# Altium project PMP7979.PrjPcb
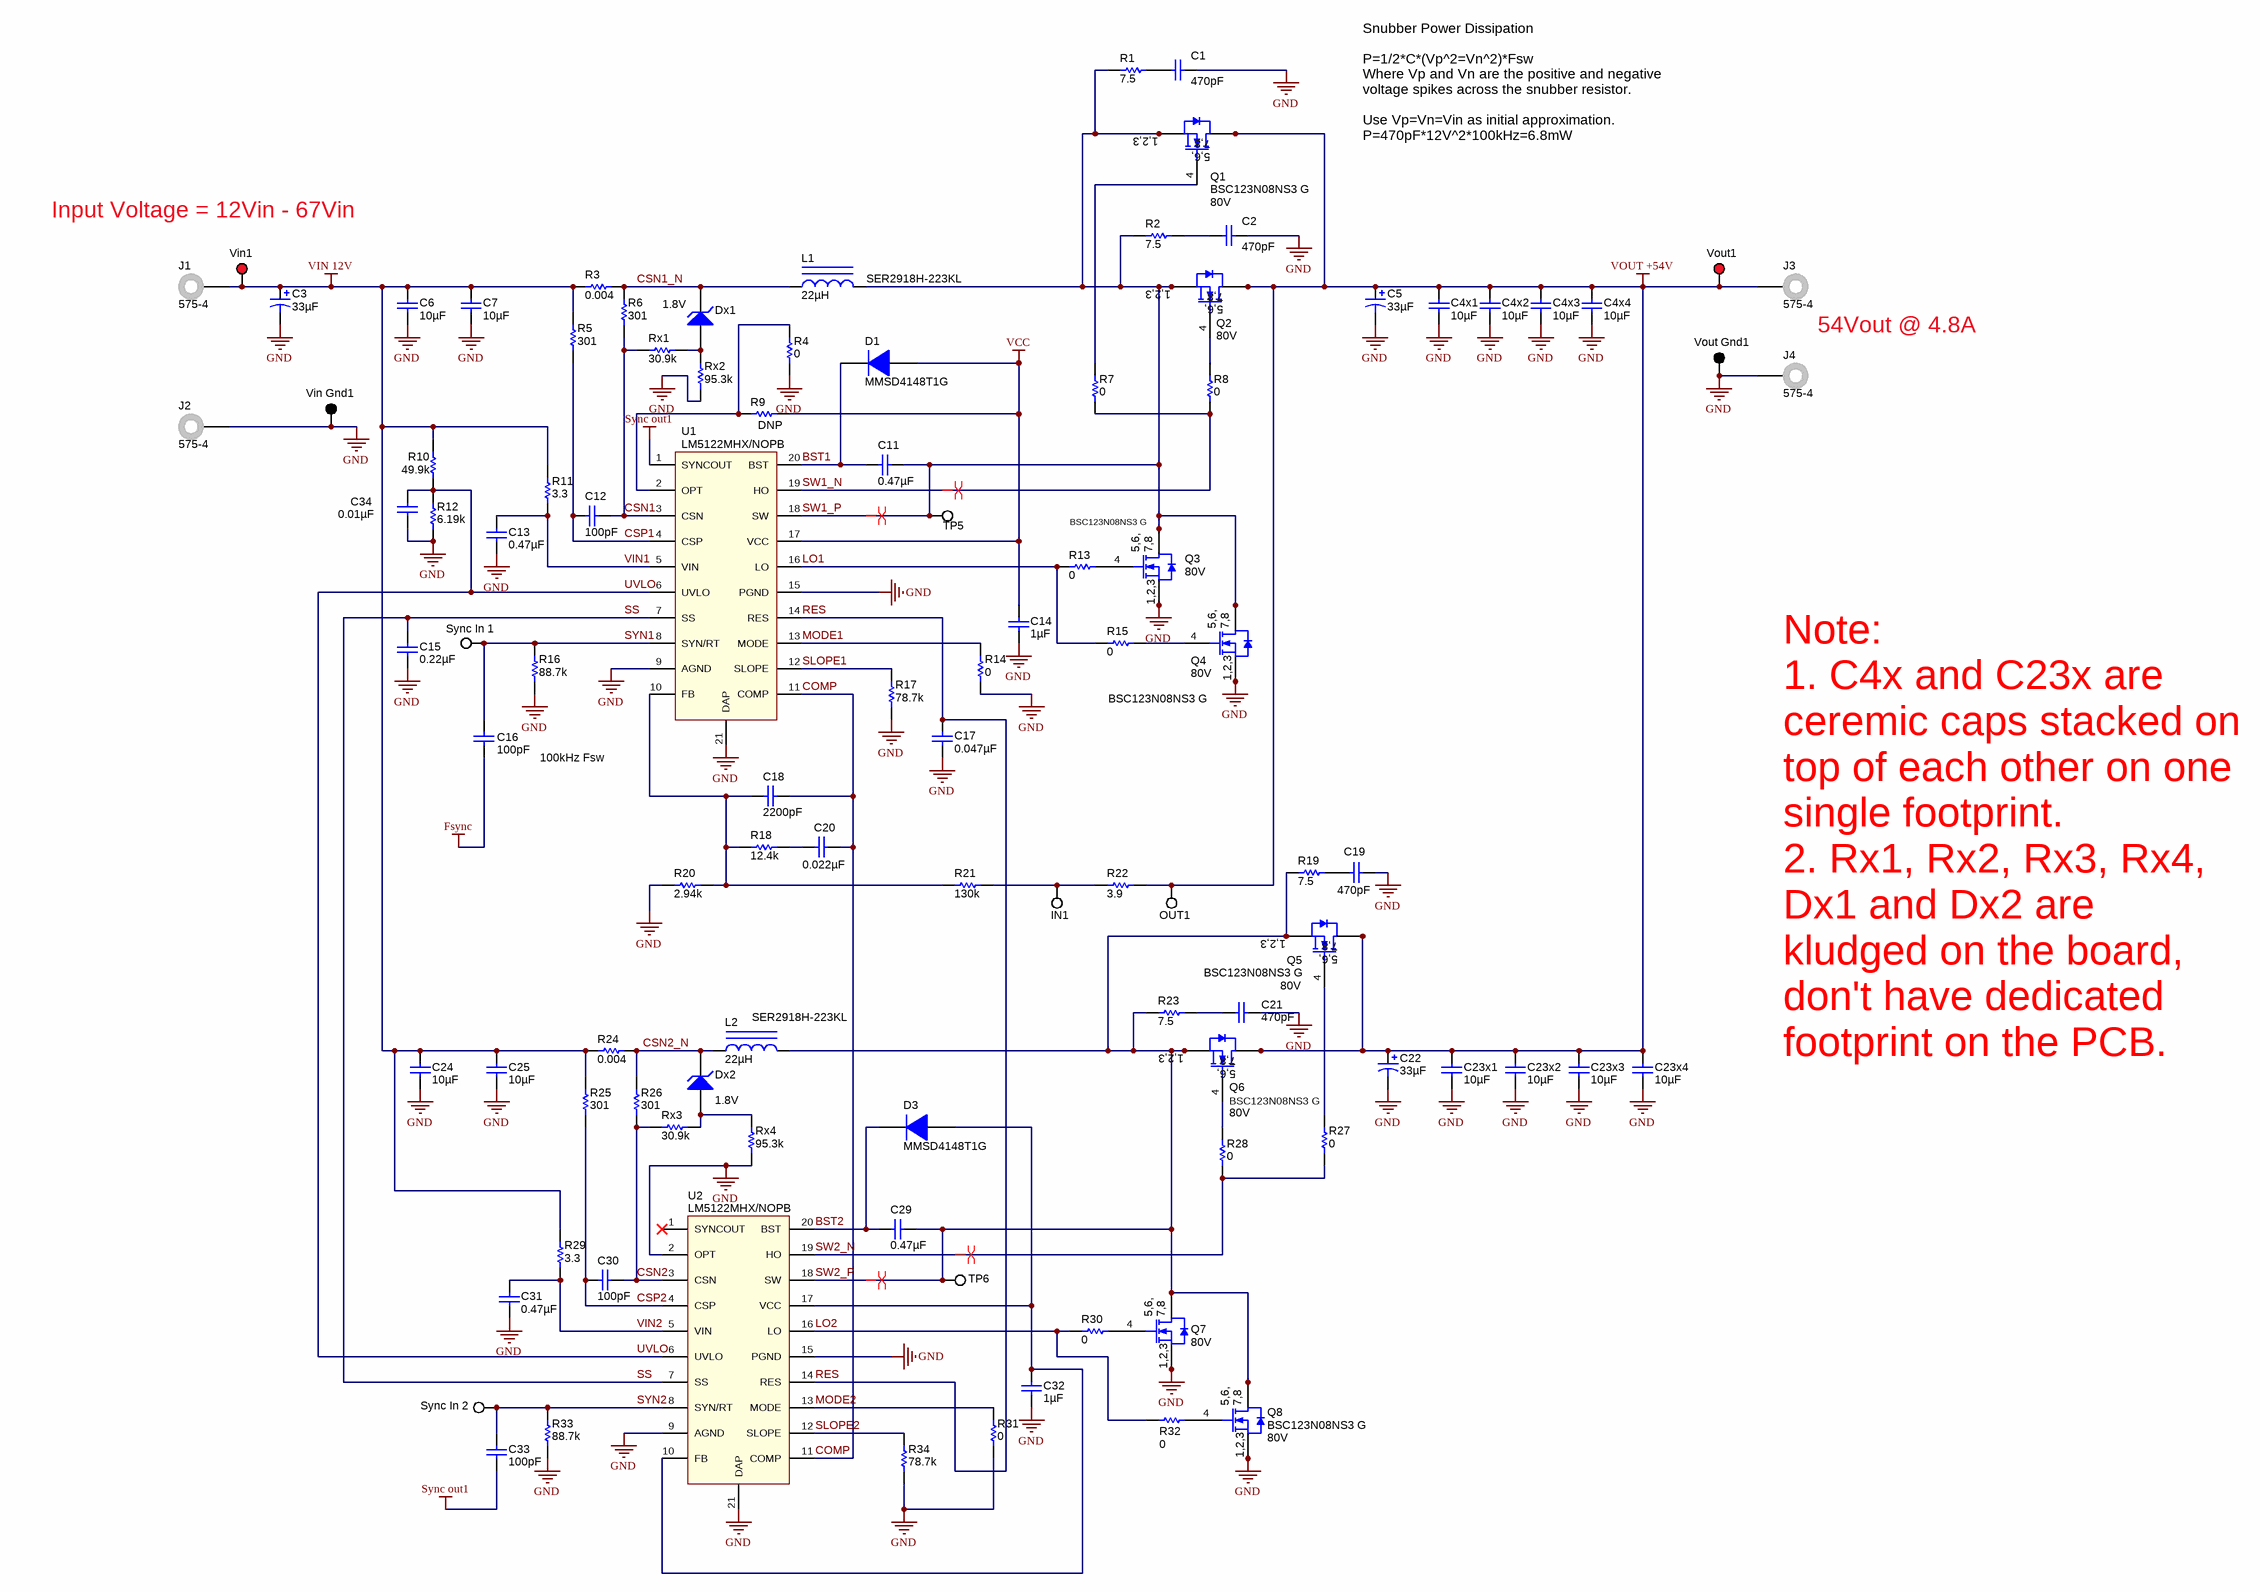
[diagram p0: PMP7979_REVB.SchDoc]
CopyrightYear: 2015; EVM_Orderable: N/A; PCB_Layout: David Baba; PCB_Rev: B; PRJ_Customer: Public Release; PRJ_Engineer: Xinyu Dai; PRJ_Number: PMP7979; PRJ_Title: LM5122 Dual Phase Boost; SCH_Rev: B; TechSupport: http://www.ti.com/support; TID: PMP7979
2 sheets, 111 parts. Net scope: global (net labels, ports and power ports of the same name join across sheets).
Board file: PMP7850 REVB.PcbDoc
Sheets:
  PMP7979_REVB.SchDoc
  PMP7979_Hardware_REVB.SchDoc

## Sheet PMP7979_REVB.SchDoc
size 558 x 431 mm; Date: Not shown in title block; ApprovedBy: Not shown in title block; CheckedBy: Not shown in title block; Author: Not shown in title block; CompanyName: Not shown in title block; Engineer: Not shown in title block; Organization: Not shown in title block; Address1: Not shown in title block; Address2: Not shown in title block; Address3: Not shown in title block; Address4: Not shown in title block; DocumentNumber: 1; Revision: Use project parameter SCH_Rev; SheetNumber: 1; SheetTotal: 2; PageSetup: Record=PageOptions¦CenterHorizontal=True¦CenterVertical=True¦PrintScale=1.00¦XCorrection=1.00¦YCorrection=1.00¦PrintKind=0¦BorderSize=5000000¦LeftOffset=0¦BottomOffset=0¦Orientation=2¦PaperLength=1000¦PaperWidth=1000¦Scale=100¦PaperSource=15¦PrintQuality=600¦MediaType=1¦DitherType=10¦PaperKind=Letter¦PrintScaleMode=1

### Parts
C1  ValueDisplayed: 470pF  [0805_HV]  (hidden comment: GRM2165C2A471JA01D)
C2  ValueDisplayed: 470pF  [0805_HV]  (hidden comment: GRM2165C2A471JA01D)
C3  ValueDisplayed: 33µF  [150CRZ_1010]  (hidden comment: MAL215097904E3)
C4x1  ValueDisplayed: 10µF  [2220_280]  (hidden comment: 22201C106MAT2A)
C4x2  ValueDisplayed: 10µF  [2220_280]  (hidden comment: 22201C106MAT2A)
C4x3  ValueDisplayed: 10µF  [2220_280]  (hidden comment: 22201C106MAT2A)
C4x4  ValueDisplayed: 10µF  [2220_280]  (hidden comment: 22201C106MAT2A)
C5  ValueDisplayed: 33µF  [150CRZ_1010]  (hidden comment: MAL215097904E3)
C6  ValueDisplayed: 10µF  [2220_280]  (hidden comment: 22201C106MAT2A)
C7  ValueDisplayed: 10µF  [2220_280]  (hidden comment: 22201C106MAT2A)
C11  ValueDisplayed: 0.47µF  [0603_HV]  (hidden comment: GRM188R71E474KA12D)
C12  ValueDisplayed: 100pF  [0603_HV]  (hidden comment: GRM1885C1H101JA01D)
C13  ValueDisplayed: 0.47µF  [0603_HV]  (hidden comment: GRM188R71E474KA12D)
C14  ValueDisplayed: 1µF  [0603_HV]  (hidden comment: GRM188R71E105KA12D)
C15  ValueDisplayed: 0.22µF  [0603_HV]  (hidden comment: GRM188R71C224KA01D)
C16  ValueDisplayed: 100pF  [0603_HV]  (hidden comment: GRM1885C1H101JA01D)
C17  ValueDisplayed: 0.047µF  [0603_HV]  (hidden comment: GRM188R71E473KA01D)
C18  ValueDisplayed: 2200pF  [0603_HV]  (hidden comment: GRM188R71E222KA01D)
C19  ValueDisplayed: 470pF  [0805_HV]  (hidden comment: GRM2165C2A471JA01D)
C20  ValueDisplayed: 0.022µF  [0603_HV]  (hidden comment: C0603C223K3RACTU)
C21  ValueDisplayed: 470pF  [0805_HV]  (hidden comment: GRM2165C2A471JA01D)
C22  ValueDisplayed: 33µF  [150CRZ_1010]  (hidden comment: MAL215097904E3)
C23x1  ValueDisplayed: 10µF  [2220_280]  (hidden comment: 22201C106MAT2A)
C23x2  ValueDisplayed: 10µF  [2220_280]  (hidden comment: 22201C106MAT2A)
C23x3  ValueDisplayed: 10µF  [2220_280]  (hidden comment: 22201C106MAT2A)
C23x4  ValueDisplayed: 10µF  [2220_280]  (hidden comment: 22201C106MAT2A)
C24  ValueDisplayed: 10µF  [2220_280]  (hidden comment: 22201C106MAT2A)
C25  ValueDisplayed: 10µF  [2220_280]  (hidden comment: 22201C106MAT2A)
C29  ValueDisplayed: 0.47µF  [0603_HV]  (hidden comment: GRM188R71E474KA12D)
C30  ValueDisplayed: 100pF  [0603_HV]  (hidden comment: GRM1885C1H101JA01D)
C31  ValueDisplayed: 0.47µF  [0603_HV]  (hidden comment: GRM188R71E474KA12D)
C32  ValueDisplayed: 1µF  [0603_HV]  (hidden comment: GRM188R71E105KA12D)
C33  ValueDisplayed: 100pF  [0603_HV]  (hidden comment: GRM1885C1H101JA01D)
C34  ValueDisplayed: 0.01µF  [0603_HV]  (hidden comment: GRM188R71C103KA01D)
D1  MMSD4148T1G  [SOD-123]
D3  MMSD4148T1G  [SOD-123]
Dx1  value 1.8V  [SOD-123]  (hidden comment: MMSZ4678T1G)
Dx2  value 1.8V  [SOD-123]  (hidden comment: MMSZ4678T1G)
IN1  5002  [Keystone5002]  (value not drawn)
J1  575-4  [Keystone_575-4]
J2  575-4  [Keystone_575-4]
J3  575-4  [Keystone_575-4]
J4  575-4  [Keystone_575-4]
L1  SER2918H-223KL  ValueDisplayed: 22µH  [SER2918H]
L2  SER2918H-223KL  ValueDisplayed: 22µH  [SER2918H]
OUT1  5002  [Keystone5002]  (value not drawn)
Q1  BSC123N08NS3 G  value 80V  [PG-TDSON-8]
Q2  value 80V  [PG-TDSON-8]  (hidden comment: BSC123N08NS3 G)
Q3  BSC123N08NS3 G  value 80V  [PG-TDSON-8]
Q4  BSC123N08NS3 G  value 80V  [PG-TDSON-8]
Q5  BSC123N08NS3 G  value 80V  [PG-TDSON-8]
Q6  BSC123N08NS3 G  value 80V  [PG-TDSON-8]
Q7  value 80V  [PG-TDSON-8]  (hidden comment: BSC123N08NS3 G)
Q8  BSC123N08NS3 G  value 80V  [PG-TDSON-8]
R1  value 7.5  [2010M]  (hidden comment: ERJ-12ZYJ7R5U)
R2  value 7.5  [2010M]  (hidden comment: ERJ-12ZYJ7R5U)
R3  ValueDisplayed: 0.004  [2512M]  (hidden comment: ERJ-M1WSF4M0U)
R4  value 0  [0603_HV]  (hidden comment: ERJ-3GEY0R00V)
R5  ValueDisplayed: 301  [0603_HV]  (hidden comment: CRCW0603301RFKEA)
R6  ValueDisplayed: 301  [0603_HV]  (hidden comment: CRCW0603301RFKEA)
R7  ValueDisplayed: 0  [0603_HV]  (hidden comment: CRCW06030000Z0EA)
R8  ValueDisplayed: 0  [0603_HV]  (hidden comment: CRCW06030000Z0EA)
R9  DNP  [0603_HV]
R10  value 49.9k  [0603_HV]  (hidden comment: CRCW060349K9FKEA)
R11  value 3.3  [0603_HV]  (hidden comment: CRCW06033R30JNEA)
R12  value 6.19k  [0603]  (hidden comment: RC0603FR-076K19L)
R13  value 0  [0603_HV]  (hidden comment: ERJ-3GEY0R00V)
R14  ValueDisplayed: 0  [0603_HV]  (hidden comment: CRCW06030000Z0EA)
R15  value 0  [0603_HV]  (hidden comment: ERJ-3GEY0R00V)
R16  ValueDisplayed: 88.7k  [0603]  (hidden comment: CRCW060388K7FKEA)
R17  ValueDisplayed: 78.7k  [0603_HV]  (hidden comment: CRCW060378K7FKEA)
R18  ValueDisplayed: 12.4k  [0603_HV]  (hidden comment: CRCW060312K4FKEA)
R19  value 7.5  [2010M]  (hidden comment: ERJ-12ZYJ7R5U)
R20  ValueDisplayed: 2.94k  [0603]  (hidden comment: CRCW06032K94FKEA)
R21  ValueDisplayed: 130k  [0603]  (hidden comment: CRCW0603130KFKEA)
R22  value 3.9  [0603]  (hidden comment: CRCW06033R90JNEA)
R23  value 7.5  [2010M]  (hidden comment: ERJ-12ZYJ7R5U)
R24  ValueDisplayed: 0.004  [2512M]  (hidden comment: ERJ-M1WSF4M0U)
R25  ValueDisplayed: 301  [0603_HV]  (hidden comment: CRCW0603301RFKEA)
R26  ValueDisplayed: 301  [0603_HV]  (hidden comment: CRCW0603301RFKEA)
R27  ValueDisplayed: 0  [0603_HV]  (hidden comment: CRCW06030000Z0EA)
R28  ValueDisplayed: 0  [0603_HV]  (hidden comment: CRCW06030000Z0EA)
R29  value 3.3  [0603_HV]  (hidden comment: CRCW06033R30JNEA)
R30  value 0  [0603_HV]  (hidden comment: ERJ-3GEY0R00V)
R31  ValueDisplayed: 0  [0603_HV]  (hidden comment: CRCW06030000Z0EA)
R32  value 0  [0603_HV]  (hidden comment: ERJ-3GEY0R00V)
R33  ValueDisplayed: 88.7k  [0603]  (hidden comment: CRCW060388K7FKEA)
R34  ValueDisplayed: 78.7k  [0603_HV]  (hidden comment: CRCW060378K7FKEA)
Rx1  ValueDisplayed: 30.9k  [0603_HV]  (hidden comment: CRCW060330K9FKEA)
Rx2  ValueDisplayed: 95.3k  [0603_HV]  (hidden comment: CRCW060395K3FKEA)
Rx3  ValueDisplayed: 30.9k  [0603_HV]  (hidden comment: CRCW060330K9FKEA)
Rx4  ValueDisplayed: 95.3k  [0603_HV]  (hidden comment: CRCW060395K3FKEA)
Sync_In_1  5002  [Keystone5002]  (value not drawn)
Sync_In_2  5002  [Keystone5002]  (value not drawn)
TP5  5002  [Keystone5002]  (value not drawn)
TP6  5002  [Keystone5002]  (value not drawn)
U1  LM5122MHX/NOPB  [MXA20A_L - 10milVia]
U2  LM5122MHX/NOPB  [MXA20A_L - 10milVia]
Vin1  5000  [Keystone5000]  (value not drawn)
Vin_Gnd1  5001  [Keystone5001]  (value not drawn)
Vout1  5000  [Keystone5000]  (value not drawn)
Vout_Gnd1  5001  [Keystone5001]  (value not drawn)

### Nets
Fsync: C16.1
GND: C1.1 C2.1 C3.2(-) C4x1.2 C4x2.2 C4x3.2 C4x4.2 C5.2(-) C6.2 C7.2 C13.2 C14.2 C15.2 C17.2 C19.1 C21.1 C22.2(-) C23x1.2 C23x2.2 C23x3.2 C23x4.2 C24.2 C25.2 C31.2 C32.2 C34.2 J2.1 J4.1 Q3.1(S) Q3.2(S) Q3.3(S) Q4.1(S) Q4.2(S) Q4.3(S) Q7.1(S) Q7.2(S) Q7.3(S) Q8.1(S) Q8.2(S) Q8.3(S) R4.1 R12.1 R14.1 R16.1 R17.1 R20.1 R31.1 R33.1 R34.1 Rx2.2 Rx4.2 U1.9(AGND) U1.15(PGND) U1.21(DAP) U2.2(OPT) U2.9(AGND) U2.15(PGND) U2.21(DAP) Vin_Gnd1.1 Vout_Gnd1.1
Sync out1: C33.1 U1.1(SYNCOUT)
VCC: C14.1 D1.2(A) R9.2 U1.17(VCC)
VIN 12V: C3.1(+) C6.1 C7.1 C24.1 C25.1 J1.1 R3.1 R5.2 R10.2 R11.2 R24.1 R25.2 R29.2 Vin1.1
VOUT +54V: C4x1.1 C4x2.1 C4x3.1 C4x4.1 C5.1(+) C22.1(+) C23x1.1 C23x2.1 C23x3.1 C23x4.1 J3.1 OUT1.1 Q1.5(D) Q1.6(D) Q1.7(D) Q1.8(D) Q1.9(D) Q2.5(D) Q2.6(D) Q2.7(D) Q2.8(D) Q2.9(D) Q5.5(D) Q5.6(D) Q5.7(D) Q5.8(D) Q5.9(D) Q6.5(D) Q6.6(D) Q6.7(D) Q6.8(D) Q6.9(D) R22.2 Vout1.1
BST1: C11.2 D1.1(K) U1.20(BST)
BST2: C29.2 D3.1(K) U2.20(BST)
COMP: C18.2 C20.2 U1.11(COMP) U2.11(COMP)
CSN1: C12.1 R6.1 Rx1.2 U1.3(CSN)
CSN1_N: Dx1.1(K) L1.1 R3.2 R6.2
CSN2: C30.1 R26.1 Rx3.2 U2.3(CSN)
CSN2_N: Dx2.1(K) L2.1 R24.2 R26.2
CSP1: C12.2 R5.1 U1.4(CSP)
CSP2: C30.2 R25.1 U2.4(CSP)
LO1: R13.2 R15.2 U1.16(LO)
LO2: R30.2 R32.2 U2.16(LO)
MODE1: R14.2 U1.13(MODE)
MODE2: R31.2 U2.13(MODE)
RES: C17.1 U1.14(RES) U2.14(RES)
SLOPE1: R17.2 U1.12(SLOPE)
SLOPE2: R34.2 U2.12(SLOPE)
SS: C15.1 U1.7(SS) U2.7(SS)
SW1_N: R7.2 R8.2 U1.19(HO)
SW1_P: C11.1 L1.2 Q1.1(S) Q1.2(S) Q1.3(S) Q2.1(S) Q2.2(S) Q2.3(S) Q3.5(D) Q3.6(D) Q3.7(D) Q3.8(D) Q3.9(D) Q4.5(D) Q4.6(D) Q4.7(D) Q4.8(D) Q4.9(D) R1.2 R2.2 TP5.1 U1.18(SW)
SW2_N: R27.2 R28.2 U2.19(HO)
SW2_P: C29.1 L2.2 Q5.1(S) Q5.2(S) Q5.3(S) Q6.1(S) Q6.2(S) Q6.3(S) Q7.5(D) Q7.6(D) Q7.7(D) Q7.8(D) Q7.9(D) Q8.5(D) Q8.6(D) Q8.7(D) Q8.8(D) Q8.9(D) R19.2 R23.2 TP6.1 U2.18(SW)
SYN1: C16.2 R16.2 Sync_In_1.1 U1.8(SYN/RT)
SYN2: C33.2 R33.2 Sync_In_2.1 U2.8(SYN/RT)
UVLO: C34.1 R10.1 R12.2 U1.6(UVLO) U2.6(UVLO)
VIN1: C13.1 R11.1 U1.5(VIN)
VIN2: C31.1 R29.1 U2.5(VIN)
NetC1_2: C1.2 R1.1
NetC2_2: C2.2 R2.1
NetC18_1: C18.1 R18.1 R20.2 R21.1 U1.10(FB)
NetC19_2: C19.2 R19.1
NetC20_1: C20.1 R18.2
NetC21_2: C21.2 R23.1
NetC32_1: C32.1 D3.2(A) U2.10(FB) U2.17(VCC)
NetDx1_2: Dx1.2(A) Rx1.1 Rx2.1
NetDx2_2: Dx2.2(A) Rx3.1 Rx4.1
NetIN1_1: IN1.1 R21.2 R22.1
NetQ1_4: Q1.4(G) R7.1
NetQ2_4: Q2.4(G) R8.1
NetQ3_4: Q3.4(G) R13.1
NetQ4_4: Q4.4(G) R15.1
NetQ5_4: Q5.4(G) R27.1
NetQ6_4: Q6.4(G) R28.1
NetQ7_4: Q7.4(G) R30.1
NetQ8_4: Q8.4(G) R32.1
NetR4_2: R4.2 R9.1 U1.2(OPT)

Not connected (* = marked no-connect by the designer): U2 1(SYNCOUT)*

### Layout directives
differential pair: SW1_N, SW1_P, SW2_N, SW2_P

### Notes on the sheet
- Snubber Power Dissipation
  P=1/2*C*(Vp^2=Vn^2)*Fsw
  Where Vp and Vn are the positive and negative voltage spikes across the snubber resistor.
  Use Vp=Vn=Vin as initial approximation.
  P=470pF*12V^2*100kHz=6.8mW
- Input Voltage = 12Vin - 67Vin
- 54Vout @ 4.8A
- 100kHz Fsw
- Note:
  1. C4x and C23x are ceremic caps stacked on top of each other on one single footprint.
  2. Rx1, Rx2, Rx3, Rx4, Dx1 and Dx2 are kludged on the board, don't have dedicated footprint on the PCB.

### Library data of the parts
C1 C2 C19 C21 = GRM2165C2A471JA01D: CAP, CERM, 470pF, 100V, +/-5%, C0G/NP0, 0805; Manufacturer: MuRata; Polarized: N; CompType: Capacitor; U/M: EA; Cap_F: 0.00000000047; Tolerance_%: 5; VDC_V: 100; TaMin_C: -55; TaMax_C: 125; Cap_Case: 0805
C3 C5 C22 = MAL215097904E3: CAP, AL, 33 µF, 100 V, +/- 20%, AEC-Q200 Grade 2, SMD; Manufacturer: Vishay-Bccomponents; Polarized: Y; CompType: Capacitor; Value: 33uF; U/M: EA; Cap_F: 0.000033; Tolerance_%: 20; Value1: Unknown; VDC_V: 100; Value2: 100V; IRMS_A: 0.25; TaMin_C: -40; TaMax_C: 105; Cap_Case: 10x10mm; AEC Category: Q200; AEC Grade: 2
C4x1-C4x4 C6 C7 C23x1-C23x4 C24 C25 = 22201C106MAT2A: CAP, CERM, 10 µF, 100 V, +/- 20%, X7R, 2220; Manufacturer: AVX; Polarized: N; CompType: Capacitor; Value: 10uF; U/M: EA; Cap_F: 0.00001; Tolerance_%: 20; Value1: Unknown; VDC_V: 100; Value2: 100V; TaMin_C: -55; TaMax_C: 125; Cap_Case: 2220; AEC Category: Q200
C11 C13 C29 C31 = GRM188R71E474KA12D: CAP, CERM, 0.47uF, 25V, +/-10%, X7R, 0603; Manufacturer: MuRata; Polarized: N; CompType: Capacitor; U/M: EA; Cap_F: 0.00000047; Tolerance_%: 10; VDC_V: 25; TaMin_C: -55; TaMax_C: 125; Cap_Case: 0603
C12 C16 C30 C33 = GRM1885C1H101JA01D: CAP, CERM, 100pF, 50V, +/-5%, C0G/NP0, 0603; Manufacturer: MuRata; Polarized: N; CompType: Capacitor; U/M: EA; Cap_F: 0.0000000001; Tolerance_%: 5; VDC_V: 50; TaMin_C: -55; TaMax_C: 125; Cap_Case: 0603
C14 C32 = GRM188R71E105KA12D: CAP, CERM, 1uF, 25V, +/-10%, X7R, 0603; Manufacturer: MuRata; Polarized: N; CompType: Capacitor; U/M: EA; Cap_F: 0.000001; Tolerance_%: 10; VDC_V: 25; TaMin_C: -55; TaMax_C: 125; Cap_Case: 0603
C15 = GRM188R71C224KA01D: CAP, CERM, 0.22 µF, 16 V, +/- 10%, X7R, 0603; Manufacturer: MuRata; Polarized: N; CompType: Capacitor; Value: 0.22uF; U/M: EA; Cap_F: 0.00000022; Tolerance_%: 10; Value1: Unknown; VDC_V: 16; Value2: 16V; TaMin_C: -55; TaMax_C: 125; Cap_Case: 0603; AEC Category: Q200
C17 = GRM188R71E473KA01D: CAP, CERM, 0.047uF, 25V, +/-10%, X7R, 0603; Manufacturer: MuRata; Polarized: N; CompType: Capacitor; U/M: EA; Cap_F: 0.000000047; Tolerance_%: 10; VDC_V: 25; TaMin_C: -55; TaMax_C: 125; Cap_Case: 0603
C18 = GRM188R71E222KA01D: CAP, CERM, 2200 pF, 25 V, +/- 10%, X7R, 0603; Manufacturer: MuRata; Polarized: N; CompType: Capacitor; Value: 2200pF; U/M: EA; Cap_F: 0.0000000022; Tolerance_%: 10; Value1: Unknown; VDC_V: 25; Value2: 25V; TaMin_C: -55; TaMax_C: 125; Cap_Case: 0603; AEC Category: Q200
C20 = C0603C223K3RACTU: CAP, CERM, 0.022uF, 25V, +/-10%, X7R, 0603; Manufacturer: Kemet; Polarized: N; CompType: Capacitor; U/M: EA; Cap_F: 0.000000022; Tolerance_%: 10; VDC_V: 25; TaMin_C: -55; TaMax_C: 125; Cap_Case: 0603
C34 = GRM188R71C103KA01D: CAP, CERM, 0.01uF, 16V, +/-10%, X7R, 0603; Manufacturer: MuRata; Polarized: N; CompType: Capacitor; U/M: EA; Cap_F: 0.00000001; Tolerance_%: 10; VDC_V: 16; TaMin_C: -55; TaMax_C: 125; Cap_Case: 0603
D1 D3 = MMSD4148T1G: Diode, Switching, 100 V, 0.2 A, SOD-123; Manufacturer: ON Semiconductor; Value: 100V; U/M: EA; Vf_V: 1; Value1: 0.2A; Value2: 1V; Io_A: 0.2; Vr_V: 100; TJmax_C: 150; AEC Category: Q101
Dx1 Dx2 = MMSZ4678T1G: Diode, Zener, 1.8 V, 500 mW, SOD-123; Manufacturer: ON Semiconductor; SymbolCreator: a0412235; U/M: EA; Power_W: 0.5; Vz_V: 1.8; Value1: 0.5W; RJA_CperW: 340; AEC Category: Q101
IN1 OUT1 Sync_In_1 Sync_In_2 TP5 TP6 = 5002: Test Point, TH, Miniature, White; Manufacturer: Keystone; Alternate Manufacturer: Any; Alternate PartNumber: Equivalent; CompType: Test Point Loop; U/M: EA
J1-J4 = 575-4: Standard Banana Jack, Uninsulated, 5.5mm; Manufacturer: Keystone; Alternate Manufacturer: Any; Alternate PartNumber: Equivalent; CompType: Connector; U/M: EA
L1 L2 = SER2918H-223KL: Inductor, Shielded E Core, Ferrite, 22 µH, 15 A, 0.0026 ohm, SMD; Manufacturer: Coilcraft; Value: 22uH; Ind_H: 22.0E-6; Imax_A: 15; Irms: 28A @ 40C rise; Isat: 15A @ 30% inductance drop; DCR_ohm: 0.0026; Value2: 15A; AEC Category: Q200
Q1-Q8 = BSC123N08NS3 G: MOSFET, N-CH, 80V, 55A, PG-TDSON-8; Manufacturer: Infineon Technologies; Alternate Manufacturer: None; U/M: EA; ChType: N; VdsMax_V: 80; Value1: 101 ohm; Rdson45_Ohm: 101; Value2: 19 nC; QgTyp_nC: 19; Vgs_V: 20; IdsMax_A: 55
R1 R2 R19 R23 = ERJ-12ZYJ7R5U: RESISTOR 7.5 OHM 3/4W 5% 2010; Manufacturer: Panasonic; Value_Code: 7R50; Tolerance_%: 5; Power_W: 1; Value2: 1W; VDC_V: 3; TempCo: -100 /+600 ppm/C; EIA_Code: E24; U/M: EA
R3 R24 = ERJ-M1WSF4M0U: RES, 0.004, 1%, 1 W, 2512; Manufacturer: Panasonic; CompType: Resistor; Value: 0.004; Value_Code: 4L000; Tolerance_%: 1; Value2: 1W; TempCo: 350 ppm/C; U/M: EA; AEC Category: Q200
R4 R13 R15 R30 R32 = ERJ-3GEY0R00V: RES, 0 ohm, 5%, 0.1W, 0603; Manufacturer: Panasonic; CompType: Resistor; Value_Code: 0000; Tolerance_%: 5; Power_W: 0.1; VDC_V: 50; TempCo: 600 ppm/C; EIA_Code: E24; U/M: EA
R5 R6 R25 R26 = CRCW0603301RFKEA: RES, 301, 1%, 0.1 W, 0603; Manufacturer: Vishay-Dale; CompType: Resistor; Value: 301; Value_Code: 301R; Tolerance_%: 1; Power_W: 0.1; Value2: 0.1W; VDC_V: 75; TempCo: 100 ppm/C; EIA_Code: E96; U/M: EA; AEC Category: Q200
R7 R8 R14 R27 R28 R31 = CRCW06030000Z0EA: RES, 0, 5%, 0.1 W, 0603; Manufacturer: Vishay-Dale; CompType: Resistor; Value: 0; Value_Code: 0000; Tolerance_%: 5; Power_W: 0.1; Value2: 0.1W; VDC_V: 75; TempCo: 200 ppm/C; EIA_Code: E24; U/M: EA; AEC Category: Q200
R9 = CRCW0603158KFKEA: RES, 158k ohm, 1%, 0.1W, 0603; Manufacturer: Vishay-Dale; CompType: Resistor; Res_ohm: 158000; Tolerance_%: 1; Power_W: 0.1; VDC_V: 75; TempCo: 100 ppm/C; EIA_Code: E96; U/M: EA
R10 = CRCW060349K9FKEA: RES, 49.9k ohm, 1%, 0.1W, 0603; Manufacturer: Vishay-Dale; CompType: Resistor; Res_ohm: 49900; Value_Code: 49k9; Tolerance_%: 1; Power_W: 0.1; VDC_V: 75; TempCo: 100 ppm/C; EIA_Code: E96; U/M: EA
R11 R29 = CRCW06033R30JNEA: RES, 3.3 ohm, 5%, 0.1W, 0603; Manufacturer: Vishay-Dale; CompType: Resistor; Value_Code: 3R30; Tolerance_%: 5; Power_W: 0.1; VDC_V: 75; TempCo: 200 ppm/C; EIA_Code: E24; U/M: EA
R12 = RC0603FR-076K19L: RES, 6.19k ohm, 1%, 0.1W, 0603; Manufacturer: Yageo America; CompType: Resistor; Res_ohm: 6190; Value_Code: 6k19; Tolerance_%: 1; Power_W: 0.1; VDC_V: 150; TempCo: 200 ppm/C; EIA_Code: E96; U/M: EA
R16 R33 = CRCW060388K7FKEA: RES, 88.7 k, 1%, 0.1 W, 0603; Manufacturer: Vishay-Dale; CompType: Resistor; Value: 88.7k; Res_ohm: 88700; Value_Code: 88k7; Tolerance_%: 1; Power_W: 0.1; Value2: 0.1W; VDC_V: 75; TempCo: 100 ppm/C; EIA_Code: E96; U/M: EA; AEC Category: Q200
R17 R34 = CRCW060378K7FKEA: RES, 78.7 k, 1%, 0.1 W, 0603; Manufacturer: Vishay-Dale; CompType: Resistor; Value: 78.7k; Res_ohm: 78700; Value_Code: 78k7; Tolerance_%: 1; Power_W: 0.1; Value2: 0.1W; VDC_V: 75; TempCo: 100 ppm/C; EIA_Code: E96; U/M: EA; AEC Category: Q200
R18 = CRCW060312K4FKEA: RES, 12.4 k, 1%, 0.1 W, 0603; Manufacturer: Vishay-Dale; CompType: Resistor; Value: 12.4k; Res_ohm: 12400; Value_Code: 12k4; Tolerance_%: 1; Power_W: 0.1; Value2: 0.1W; VDC_V: 75; TempCo: 100 ppm/C; EIA_Code: E96; U/M: EA; AEC Category: Q200
R20 = CRCW06032K94FKEA: RES, 2.94 k, 1%, 0.1 W, 0603; Manufacturer: Vishay-Dale; CompType: Resistor; Value: 2.94k; Res_ohm: 2940; Value_Code: 2k94; Tolerance_%: 1; Power_W: 0.1; Value2: 0.1W; VDC_V: 75; TempCo: 100 ppm/C; EIA_Code: E96; U/M: EA; AEC Category: Q200
R21 = CRCW0603130KFKEA: RES, 130 k, 1%, 0.1 W, 0603; Manufacturer: Vishay-Dale; CompType: Resistor; Value: 130k; Res_ohm: 130000; Tolerance_%: 1; Power_W: 0.1; Value2: 0.1W; VDC_V: 75; TempCo: 100 ppm/C; EIA_Code: E96; U/M: EA; AEC Category: Q200
R22 = CRCW06033R90JNEA: RES, 3.9 ohm, 5%, 0.1W, 0603; Manufacturer: Vishay-Dale; CompType: Resistor; Value_Code: 3R90; Tolerance_%: 5; Power_W: 0.1; VDC_V: 75; TempCo: 200 ppm/C; EIA_Code: E24; U/M: EA
Rx1 Rx3 = CRCW060330K9FKEA: RES, 30.9 k, 1%, 0.1 W, 0603; Manufacturer: Vishay-Dale; CompType: Resistor; Value: 30.9k; Res_ohm: 30900; Value_Code: 30k9; Tolerance_%: 1; Power_W: 0.1; Value2: 0.1W; VDC_V: 75; TempCo: 100 ppm/C; EIA_Code: E96; U/M: EA; AEC Category: Q200
Rx2 Rx4 = CRCW060395K3FKEA: RES, 95.3 k, 1%, 0.1 W, 0603; Manufacturer: Vishay-Dale; CompType: Resistor; Value: 95.3k; Res_ohm: 95300; Value_Code: 95k3; Tolerance_%: 1; Power_W: 0.1; Value2: 0.1W; VDC_V: 75; TempCo: 100 ppm/C; EIA_Code: E96; U/M: EA; AEC Category: Q200
U1 U2 = LM5122MHX/NOPB: Wide Input Synchronous Boost Controller with Multiple Phase Capability, PWP0020A; Manufacturer: Texas Instruments; Alternate PartNumber: LM5122MHE/NOPB; SymbolCreator: a0411947; CompType: IC; U/M: EA
Vin1 Vout1 = 5000: Test Point, TH, Miniature, Red; Manufacturer: Keystone; CompType: Test Point Loop; U/M: EA
Vin_Gnd1 Vout_Gnd1 = 5001: Test Point, TH, Miniature, Black; Manufacturer: Keystone; CompType: Test Point Loop; U/M: EA

## Sheet PMP7979_Hardware_REVB.SchDoc
size 431 x 279 mm; Date: Not shown in title block; ApprovedBy: Not shown in title block; CheckedBy: Not shown in title block; Author: Not shown in title block; CompanyName: Not shown in title block; Engineer: Not shown in title block; Organization: Not shown in title block; Address1: Not shown in title block; Address2: Not shown in title block; Address3: Not shown in title block; Address4: Not shown in title block; DocumentNumber: 2; Revision: Use project parameter SCH_Rev; SheetNumber: 2; SheetTotal: 2; PageSetup: Record=PageOptions¦CenterHorizontal=True¦CenterVertical=True¦PrintScale=1.00¦XCorrection=1.00¦YCorrection=1.00¦PrintKind=0¦BorderSize=5000000¦LeftOffset=0¦BottomOffset=0¦Orientation=2¦PaperLength=1000¦PaperWidth=1000¦Scale=100¦PaperSource=15¦PrintQuality=600¦MediaType=1¦DitherType=10¦PaperKind=Letter¦PrintScaleMode=1
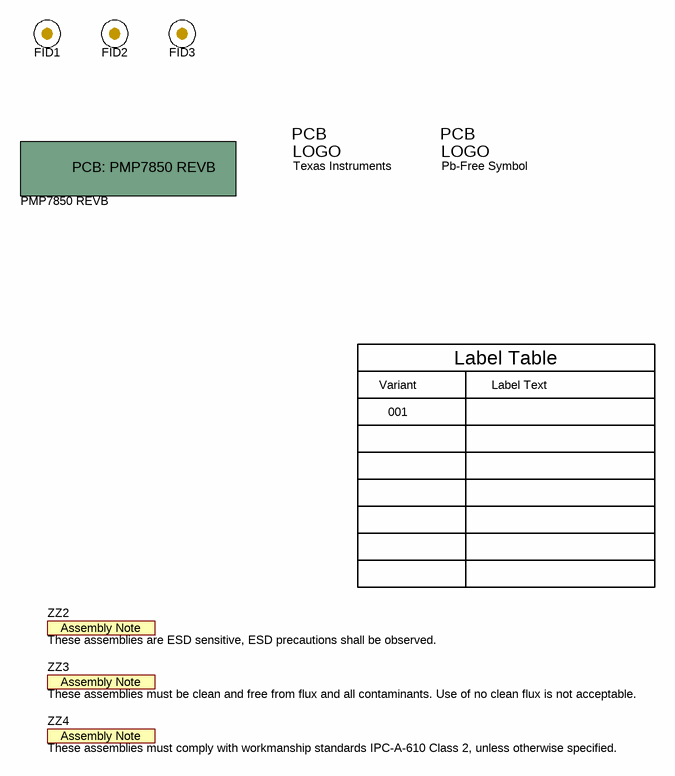
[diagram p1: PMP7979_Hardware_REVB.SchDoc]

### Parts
!PCB?  PMP7850 REVB  (mechanical)
FID1  Fiducial  [Fiducial10-20]  (value not drawn)
FID2  Fiducial  [Fiducial10-20]  (value not drawn)
FID3  Fiducial  [Fiducial10-20]  (value not drawn)
Logo1  Texas Instruments  [TI_Stacked_Overlay_Small]  (no BOM)
Logo2  Pb-Free Symbol  [Pb-Free_Overlay_Small]  (no BOM)
ZZ2  These assemblies are ESD sensitive, ESD precautions shall be observed.  [AssemblyNote]  (no BOM)
ZZ3  These assemblies must be clean and free from flux and all contaminants. Use of no clean flux is not acceptable.  [AssemblyNote]  (no BOM)
ZZ4  These assemblies must comply with workmanship standards IPC-A-610 Class 2, unless otherwise specified.  [AssemblyNote]  (no BOM)

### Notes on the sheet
- Variant
- Label Table
- Label Text
- 001

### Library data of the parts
!PCB? = PCB_OtherProject: Manufacturer: Any; SymbolCreator: a0412235; CompType: PCB; U/M: EA
FID1-FID3 = Fiducial: Fiducial mark.  There is nothing to buy or mount.; SymbolCreator: codlsc
Logo1 = TI_Logo: Texas Instrument Corporate Signature; SymbolCreator: codlsc
Logo2 = Pb-Free: SymbolCreator: a0412235
ZZ2-ZZ4 = AssemblyNote: SymbolCreator: codlsc

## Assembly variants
001: not fitted FID1 FID2 FID3 R9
